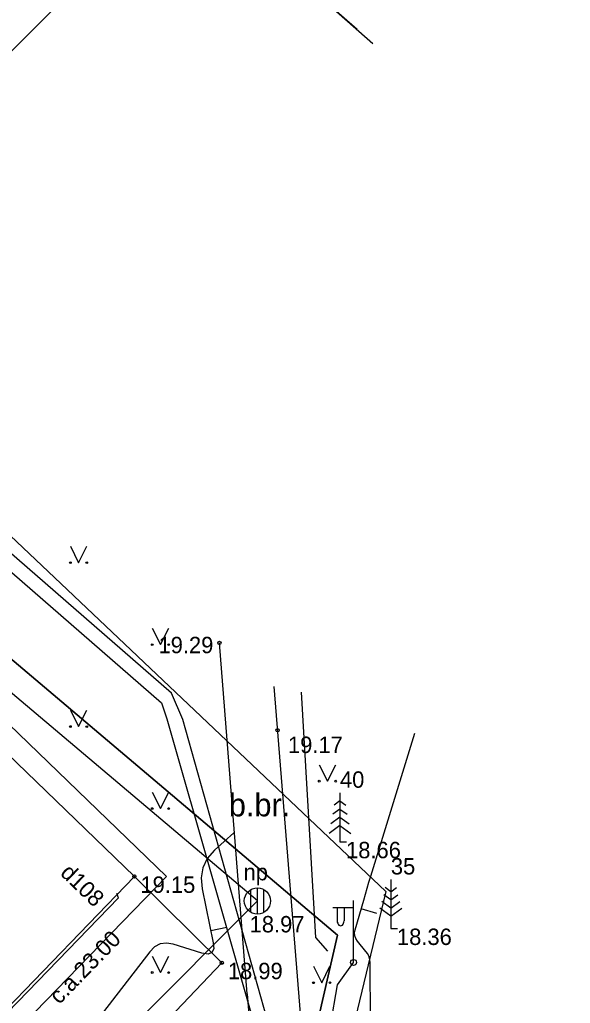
# Model space of a CAD drawing. Extents: x 532933 to 533143, y 328014 to 328163.
# Drawn here: x 533028.2 to 533045, y 328066.56 to 328096.56 of the extents above; entities that cross this region are included whole.
import ezdxf

# ---------------------------------------------------------------- set-up
doc = ezdxf.new("R2010")
doc.units = 0
for name, color, linetype in [('APGS_ELEM_####_####_#', 7, 'Continuous'), ('APGS_VADP_ZSPR_####_#', 7, 'Continuous'), ('BUVE_EKAS_####_####_#', 7, 'Continuous'), ('CELI_CMAL_####_####_#', 7, 'Continuous'), ('CELI_CSEG_####_TKST_#', 7, 'Continuous'), ('GAZE_VADV_ASP1_####_#', 7, 'Continuous'), ('GAZE_VADV_ASP1_TKST_#', 7, 'Continuous'), ('LKAN_ELEM_####_####_#', 7, 'Continuous'), ('LKAN_ELEM_PAST_TKST_#', 7, 'Continuous'), ('LKAN_VADP_PAST_####_#', 7, 'Continuous'), ('NORB_ZOGS_ZSTP_####_#', 7, 'Continuous'), ('RAMI_UZMR_####_####_#', 7, 'Continuous'), ('RELJ_AATZ_####_TKST_#', 7, 'Continuous'), ('RELJ_ELEM_####_####_#', 7, 'Continuous'), ('RELJ_HORZ_PAMT_####_#', 7, 'Continuous'), ('ROBZ_PROJ_####_####_#', 7, 'Continuous'), ('ROBZ_UZMR_####_####_#', 7, 'Continuous'), ('SILT_VADP_UDEN_####_#', 7, 'Continuous'), ('TERT_DIAM_####_TKST_#', 7, 'Continuous'), ('TERT_ELEM_####_####_#', 7, 'Continuous')]:
    doc.layers.add(name, color=color, linetype=linetype)

msp = doc.modelspace()

# ---------------------------------------------------------------- linework, layer by layer
at = {"layer": 'APGS_ELEM_####_####_#'}
for p, q in [((533038.39, 328067.81), (533038.39, 328069.693)), ((533038.39, 328069.477), (533037.755, 328069.472)), ((533037.89, 328069.473), (533037.89, 328069.081)), ((533038.1, 328069.475), (533038.1, 328069.081))]:
    msp.add_line(p, q, dxfattribs=at)
msp.add_circle((533038.39, 328067.81), 0.09, dxfattribs=at)
msp.add_ellipse((533037.995, 328069.081), major_axis=(0, 0.151), ratio=0.695971, start_param=1.570796, end_param=4.712389, dxfattribs=at)
at = {"layer": 'APGS_VADP_ZSPR_####_#'}
for points in [[(533037.602, 328068.152), (533037.235, 328068.573), (533036.805, 328076.047)], [(533039.109, 328054.708), (533038.039, 328062.204), (533037.683, 328065.881), (533037.897, 328067.13), (533038.39, 328067.81)]]:
    msp.add_lwpolyline(points, dxfattribs=at)
at = {"layer": 'BUVE_EKAS_####_####_#'}
msp.add_line((533019.634, 328057.914), (533031.702, 328070.431), dxfattribs=at)
msp.add_lwpolyline([(533031.702, 328070.431), (533021.227, 328080.543), (533009.143, 328068.025)], dxfattribs=at)
at = {"layer": 'CELI_CMAL_####_####_#'}
for p, q in [((533035.146, 328066.848), (533034.299, 328077.552)), ((533036.849, 328065.271), (533035.963, 328076.225))]:
    msp.add_line(p, q, dxfattribs=at)
for points in [[(533012.79, 328072.656), (533021.244, 328081.474), (533032.683, 328070.432)], [(533032.683, 328070.432), (533019.631, 328056.99), (533008.246, 328067.854)], [(533035.146, 328066.848), (533035.486, 328062.547)]]:
    msp.add_lwpolyline(points, dxfattribs=at)
at = {"layer": 'GAZE_VADV_ASP1_####_#'}
for p, q in [((533031.217, 328069.776), (533031.169, 328069.908)), ((533019.535, 328057.737), (533031.217, 328069.776))]:
    msp.add_line(p, q, dxfattribs=at)
at = {"layer": 'LKAN_ELEM_####_####_#'}
for p, q in [((533035.256, 328069.338), (533035.256, 328070.03)), ((533035.456, 328069.284), (533035.456, 328070.084)), ((533035.656, 328069.338), (533035.656, 328070.03))]:
    msp.add_line(p, q, dxfattribs=at)
msp.add_circle((533035.456, 328069.684), 0.4, dxfattribs=at)
at = {"layer": 'LKAN_VADP_PAST_####_#'}
for p, q in [((533035.456, 328069.684), (533020.443, 328082.363)), ((533021.731, 328055.94), (533035.456, 328069.684))]:
    msp.add_line(p, q, dxfattribs=at)
at = {"layer": 'NORB_ZOGS_ZSTP_####_#'}
msp.add_lwpolyline([(533031.702, 328070.431), (533034.369, 328067.798), (533022.758, 328055.608)], dxfattribs=at)
at = {"layer": 'RAMI_UZMR_####_####_#'}
msp.add_lwpolyline([(532947.854, 328059.458), (532970.012, 328105.269), (532980.164, 328130.66), (532983.041, 328140.509), (533003.397, 328153.917), (533034.71, 328122.623), (533045.001, 328112.629), (533020.332, 328088.009), (533039.378, 328069.977), (533029.682, 328029.753), (533016.724, 328021.343), (532947.854, 328059.458)], dxfattribs=at)
at = {"layer": 'RELJ_ELEM_####_####_#'}
for centre in [(533034.299, 328077.552), (533036.071, 328074.888), (533031.702, 328070.431), (533034.369, 328067.798)]:
    msp.add_circle(centre, 0.05, dxfattribs=at)
at = {"layer": 'RELJ_HORZ_PAMT_####_#'}
for p, q in [((533039.101, 328069.305), (533038.62, 328069.443)), ((533034.523, 328068.877), (533034.033, 328068.775))]:
    msp.add_line(p, q, dxfattribs=at)
for points in [[(533038.927, 328062.49), (533038.893, 328067.794), (533038.884, 328067.891), (533038.86, 328067.982), (533038.82, 328068.068), (533038.764, 328068.147), (533038.508, 328068.455), (533038.456, 328068.534), (533038.426, 328068.618), (533038.419, 328068.707), (533038.436, 328068.801), (533038.697, 328069.709), (533038.75, 328069.892), (533038.804, 328070.075), (533038.858, 328070.257), (533038.914, 328070.44), (533040.256, 328074.803)], [(533034.732, 328071.758), (533034.15, 328071.232), (533033.928, 328070.979), (533033.79, 328070.699), (533033.737, 328070.391), (533033.767, 328070.056), (533034.109, 328068.411), (533034.122, 328068.223), (533034.069, 328068.108), (533033.95, 328068.066), (533033.764, 328068.096), (533032.889, 328068.363), (533032.68, 328068.398), (533032.491, 328068.372), (533032.321, 328068.284), (533032.171, 328068.134), (533028.755, 328063.714)]]:
    msp.add_lwpolyline(points, dxfattribs=at)
at = {"layer": 'ROBZ_PROJ_####_####_#'}
msp.add_line((533038.5, 328096.255), (533029.138, 328104.514), dxfattribs=at)
at = {"layer": 'ROBZ_UZMR_####_####_#'}
msp.add_lwpolyline([(532993.949, 328071.405), (532999.253, 328076.841), (533001.874, 328079.871), (533025.763, 328107.492), (533029.138, 328104.514), (533014.917, 328088.072), (533037.903, 328068.645), (533030.421, 328036.082)], close=True, dxfattribs=at)
msp.add_lwpolyline([(533030.97, 328020.652), (533020.389, 328026.352), (533029.157, 328030.58), (533030.421, 328036.082), (533037.903, 328068.645), (533014.917, 328088.072), (533029.138, 328104.514), (533038.98, 328095.831)], dxfattribs=at)
at = {"layer": 'SILT_VADP_UDEN_####_#'}
for points in [[(533004.853, 328045.947), (533019.384, 328034.966), (533019.749, 328035.185), (533031.003, 328047.839), (533031.356, 328048.225), (533031.335, 328048.654), (533025.793, 328053.779), (533025.755, 328054.215), (533035.838, 328064.377), (533036.105, 328064.808), (533033.176, 328075.216), (533032.836, 328076.021), (533015.446, 328091.145), (533015.462, 328091.585), (533029.065, 328106.172), (533029.033, 328106.692), (533017.302, 328118.3), (533000, 328134.38)], [(533000, 328133.784), (533016.764, 328118.182), (533028.476, 328106.559), (533028.508, 328106.039), (533014.85, 328091.596), (533014.892, 328091.077), (533032.527, 328075.724), (533032.689, 328075.239), (533035.542, 328065.283), (533035.311, 328064.711), (533024.98, 328054.226), (533025.028, 328053.821), (533027.938, 328051.227), (533030.653, 328048.689), (533030.642, 328048.162), (533019.754, 328035.526), (533019.215, 328035.483), (533005.473, 328047.022)]]:
    msp.add_lwpolyline(points, dxfattribs=at)
at = {"layer": 'TERT_ELEM_####_####_#'}
for p, q in [((533029.75, 328080.5), (533030, 328080)), ((533030, 328080), (533030.25, 328080.5)), ((533032.25, 328078), (533032.5, 328077.5)), ((533032.5, 328077.5), (533032.75, 328078)), ((533029.75, 328075.5), (533030, 328075)), ((533030, 328075), (533030.25, 328075.5)), ((533037.343, 328073.836), (533037.593, 328073.336)), ((533037.593, 328073.336), (533037.843, 328073.836)), ((533032.25, 328073), (533032.5, 328072.5)), ((533032.5, 328072.5), (533032.75, 328073)), ((533037.974, 328072.986), (533037.974, 328071.486)), ((533037.974, 328072.736), (533037.798, 328072.608)), ((533037.974, 328072.736), (533038.148, 328072.608)), ((533037.974, 328072.486), (533037.758, 328072.328)), ((533037.974, 328072.486), (533038.19, 328072.328)), ((533037.974, 328071.986), (533037.642, 328071.742)), ((533037.974, 328072.236), (533037.696, 328072.032)), ((533037.974, 328072.236), (533038.252, 328072.032)), ((533037.974, 328071.986), (533038.308, 328071.742)), ((533037.974, 328071.486), (533038.174, 328071.486)), ((533039.527, 328070.341), (533039.527, 328068.841)), ((533039.527, 328069.715), (533039.311, 328069.873)), ((533039.527, 328069.965), (533039.351, 328070.093)), ((533039.527, 328069.965), (533039.701, 328070.093)), ((533039.527, 328069.715), (533039.743, 328069.873)), ((533039.527, 328069.465), (533039.249, 328069.669)), ((533039.527, 328069.465), (533039.805, 328069.669)), ((533039.527, 328069.215), (533039.195, 328069.459)), ((533039.527, 328069.215), (533039.861, 328069.459)), ((533039.527, 328068.841), (533039.727, 328068.841)), ((533032.25, 328068), (533032.5, 328067.5)), ((533032.5, 328067.5), (533032.75, 328068)), ((533037.17, 328067.691), (533037.42, 328067.191)), ((533037.42, 328067.191), (533037.67, 328067.691))]:
    msp.add_line(p, q, dxfattribs=at)
for centre, radius in [((533029.75, 328080), 0.028), ((533030.25, 328080), 0.0263), ((533032.25, 328077.5), 0.028), ((533032.75, 328077.5), 0.0263), ((533029.75, 328075), 0.028), ((533030.25, 328075), 0.0263), ((533037.343, 328073.336), 0.028), ((533037.843, 328073.336), 0.0263), ((533032.25, 328072.5), 0.028), ((533032.75, 328072.5), 0.0263), ((533032.25, 328067.5), 0.028), ((533032.75, 328067.5), 0.0263), ((533037.169, 328067.191), 0.028), ((533037.669, 328067.191), 0.0263)]:
    msp.add_circle(centre, radius, dxfattribs=at)

# ---------------------------------------------------------------- texts
at = {"layer": 'CELI_CSEG_####_TKST_#'}
msp.add_text('b.br.', height=0.7, dxfattribs=at).set_placement((533034.584, 328072.264))
at = {"layer": 'GAZE_VADV_ASP1_TKST_#'}
for s, rotation, p in [('d108', 315.8622, (533029.413, 328070.502)), ('c.a.23.00', 45.8622, (533029.412, 328066.508))]:
    msp.add_text(s, height=0.5, rotation=rotation, dxfattribs=at).set_placement(p)
at = {"layer": 'LKAN_ELEM_PAST_TKST_#'}
for s, p in [('np', (533035.033, 328070.312)), (' 18.97', (533035.033, 328068.725))]:
    msp.add_text(s, height=0.5, dxfattribs=at).set_placement(p)
at = {"layer": 'RELJ_AATZ_####_TKST_#'}
for s, p in [(' 19.29', (533032.253, 328077.239)), (' 19.17', (533036.203, 328074.195)), (' 18.66', (533037.974, 328070.986)), (' 19.15', (533031.702, 328069.931)), (' 18.36', (533039.527, 328068.341)), (' 18.99', (533034.369, 328067.298))]:
    msp.add_text(s, height=0.5, dxfattribs=at).set_placement(p)
at = {"layer": 'TERT_DIAM_####_TKST_#'}
for s, p in [('40', (533037.974, 328073.136)), ('35', (533039.527, 328070.491))]:
    msp.add_text(s, height=0.5, dxfattribs=at).set_placement(p)

doc.saveas('drawing.dxf')
